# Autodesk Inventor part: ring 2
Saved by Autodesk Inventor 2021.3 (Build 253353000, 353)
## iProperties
Created: 2022-02
Part Number: ring 2
Material: Generic
Document SubType Name: Modeling
Designer: Administrator
Density: 1 g/cm^3
Appearance: Default
Title: ring 2
Author: Administrator
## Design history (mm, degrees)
feature "Body1"
body "Solid1"
